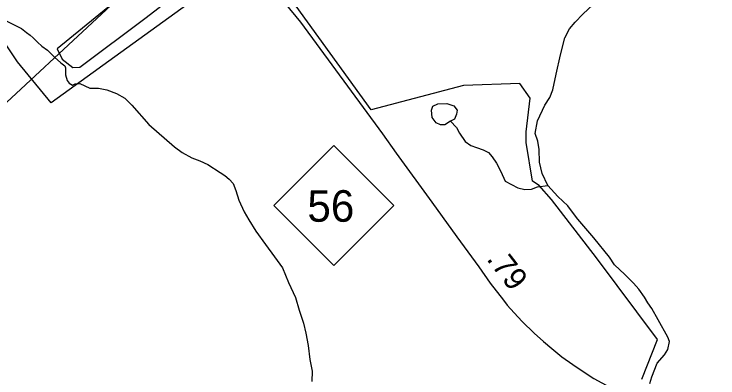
# Model space of a CAD drawing. Extents: x 2056842 to 2160602, y 826753 to 1016856.
# Drawn here: x 2083435 to 2087342, y 866279 to 868296 of the extents above; entities that cross this region are included whole.
import ezdxf

# ---------------------------------------------------------------- set-up
doc = ezdxf.new("R2010")
doc.units = 0
for name, color, linetype in [('Exist Boundary Political City Limit New', 7, 'Continuous'), ('Exist Hydrographic Creek Single Shore', 7, 'Continuous'), ('Exist Hydrographic Lake Shore', 7, 'Continuous'), ('Exist Hydrographic Misc Water Feature', 7, 'Continuous'), ('Exist Road Non-System Type 51', 7, 'Continuous'), ('Exist Road Primary NC Attributed', 7, 'Continuous'), ('Exist Road Primary NC Service Mileage Hundredths English Label', 7, 'Continuous'), ('Exist Road Primary NC Shield CELL', 7, 'Continuous'), ('Exist Road Primary NC Shield Number Label', 7, 'Continuous'), ('Exist Utilities Telephone Line', 7, 'Continuous'), ('Map Preparation Boundary City Limit Buffer Line', 7, 'Continuous')]:
    doc.layers.add(name, color=color, linetype=linetype)

msp = doc.modelspace()

# ---------------------------------------------------------------- linework, layer by layer
at = {"layer": 'Exist Boundary Political City Limit New'}
for points in [[(2084714.8, 868581.4), (2083641.4, 867804.3), (2083454, 868032.2), (2083299.9, 868259.2)], [(2086919.5, 866272.4), (2087006.9, 866490.9), (2086667, 866945.4), (2086417.6, 867267.5), (2086349.6, 867344.8), (2086312.8, 867368.8), (2086278.1, 867585), (2086277.5, 867638.4), (2086278, 867643.6), (2086299.9, 867830.6), (2086242.6, 867911.6), (2085930.4, 867900.1), (2085416.8, 867765.6), (2085000, 868339.6)]]:
    msp.add_lwpolyline(points, dxfattribs=at)
at = {"layer": 'Exist Hydrographic Creek Single Shore'}
msp.add_lwpolyline([(2083349.9, 868279.4), (2083438.3, 868235.6), (2083476, 868215.6), (2083504.3, 868193.9), (2083524.2, 868180), (2083540.2, 868164.2), (2083564.2, 868140.2), (2083588.6, 868118.2), (2083620.8, 868096.4), (2083658.5, 868057.6), (2083693.5, 868025.1), (2083716, 868010.1), (2083719.8, 867997.6), (2083721, 867960.1), (2083729.8, 867927.6), (2083741, 867912.6), (2083758.5, 867902.6), (2083773.5, 867910.1), (2083799.7, 867911.3), (2083856, 867886.3), (2083903.4, 867886.3), (2083949.7, 867876.3), (2084003.4, 867855.1), (2084049.6, 867830.7), (2084089.3, 867792), (2084182.1, 867683.2), (2084326.1, 867560.5), (2084368.4, 867528.5), (2084422.5, 867498.9), (2084466.6, 867483.2), (2084510.1, 867461.3), (2084578.5, 867417.6), (2084604.6, 867401.4), (2084628.6, 867381.6), (2084650.9, 867357.5), (2084666.7, 867317.7), (2084682.9, 867263.8), (2084711.4, 867199.8), (2084737.3, 867156.1), (2084777.4, 867092), (2084829.7, 867018.3), (2084880.2, 866950.3), (2084924.3, 866888.3), (2084958.3, 866806.9), (2084996.9, 866724.8), (2085016.5, 866654.9), (2085041.1, 866582.9), (2085055.3, 866526.8), (2085067.2, 866458.9), (2085076, 866381.2), (2085089.5, 866315.1), (2085087.9, 866258.9)], dxfattribs=at)
at = {"layer": 'Exist Hydrographic Lake Shore'}
for points in [[(2086397.4, 867345.2), (2086366.2, 867411.5), (2086352.4, 867475.2), (2086349.8, 867544.9), (2086341.5, 867590.7), (2086327.4, 867634.1), (2086339.9, 867704.2), (2086381.2, 867790.4), (2086408.6, 867834.2), (2086426.1, 867876.7), (2086444.9, 867962.8), (2086468.6, 868070.3), (2086492.4, 868164.1), (2086517.3, 868215.4), (2086549.8, 868251.6), (2086592.3, 868296.6), (2086648.5, 868350.4), (2086678.5, 868383.5), (2086714.8, 868431), (2086733.5, 868468.5), (2086742.3, 868506)], [(2086964.7, 866247.4), (2086974.7, 866283.7), (2087004.6, 866360), (2087045.9, 866406.2), (2087064.6, 866436.2), (2087073.4, 866481.2), (2087063.4, 866503.7), (2087010.9, 866601.2), (2086974.7, 866662.6), (2086953.4, 866695.1), (2086934.3, 866726.7), (2086902, 866770.7), (2086873.9, 866804.7), (2086826, 866852.3), (2086767.7, 866906.3), (2086739.4, 866948.3), (2086652.3, 867054.9), (2086563.6, 867158.7), (2086539.8, 867190.2), (2086508.6, 867232.7), (2086453.6, 867284), (2086397.4, 867345.2)]]:
    msp.add_lwpolyline(points, dxfattribs=at)
at = {"layer": 'Exist Hydrographic Misc Water Feature'}
for points in [[(2085857.6, 867701.7), (2085825.1, 867682.9), (2085801.4, 867682.9), (2085777.7, 867692.9), (2085756.4, 867722.9), (2085751.4, 867764.2), (2085760.2, 867785.4), (2085786.4, 867799.2), (2085836.4, 867800.4), (2085875.1, 867786.7), (2085893.9, 867762.9), (2085891.4, 867740.4), (2085880.1, 867714.2), (2085857.6, 867701.7)], [(2085857.6, 867701.7), (2085891.5, 867667.7), (2085907.5, 867635.6), (2085939.7, 867589.8), (2085969.6, 867567.8), (2086001.8, 867556.1), (2086037.9, 867544.1), (2086068, 867528.1), (2086088.3, 867504.4), (2086111.9, 867470.4), (2086136.3, 867422.4), (2086160.3, 867370.5), (2086231.2, 867332.7), (2086269.9, 867322.7), (2086306.2, 867325.2), (2086339.9, 867337.7), (2086397.4, 867345.2)]]:
    msp.add_lwpolyline(points, dxfattribs=at)
at = {"layer": 'Exist Road Non-System Type 51'}
msp.add_lwpolyline([(2084593.6, 868819.8), (2084372.1, 868648), (2083954.7, 868332.1), (2083674.3, 868103.5), (2083702.3, 868046.3), (2083760.5, 868000.6), (2083799.9, 868002.7), (2084167.5, 868277), (2084694.1, 868683.5)], dxfattribs=at)
at = {"layer": 'Exist Road Primary NC Attributed'}
msp.add_lwpolyline([(2084851.1, 868465), (2085025.1, 868251.2), (2085479.5, 867632.3), (2085556.7, 867525.5), (2085753.1, 867254.1), (2085810.8, 867172.9), (2085891.9, 867061.6), (2086014.4, 866893.7), (2086077.1, 866804.8), (2086151, 866709.1), (2086172.2, 866681.6), (2086210.8, 866638.6), (2086255.1, 866591), (2086322.8, 866526.1), (2086373.1, 866481.3), (2086420.7, 866441), (2086476.1, 866396.3), (2086536, 866352.6), (2086604.8, 866307.3), (2086654, 866275.4), (2086854.9, 866166.9), (2086913.1, 866138.3), (2086965.1, 866108.7), (2087019.4, 866084)], dxfattribs=at)
at = {"layer": 'Exist Road Primary NC Shield CELL'}
msp.add_lwpolyline([(2084876, 867234.4), (2085209, 867567.4), (2085542, 867234.4), (2085209, 866901.4)], close=True, dxfattribs=at)
at = {"layer": 'Exist Utilities Telephone Line'}
msp.add_lwpolyline([(2070574.6, 855889.8), (2073540.2, 858741.1), (2079471.4, 864196.3), (2082575.1, 867047.6), (2086740, 870917.2), (2087764.9, 872677.4), (2089015.1, 875921.4), (2089705.6, 877143.4), (2092053.4, 881391.2), (2094430.2, 885697.2), (2096843.4, 888330.3), (2097766.5, 889363.1), (2100637.6, 891101.5), (2103123.5, 892599.9), (2104820.7, 893625.5), (2107244.8, 895109.3), (2108287.8, 895378.4), (2108625.8, 895633), (2109723.4, 896782.2), (2110232.2, 897204.1), (2110707.5, 898076.3)], dxfattribs=at)
at = {"layer": 'Map Preparation Boundary City Limit Buffer Line'}
for points in [[(2084714.8, 868581.4), (2083641.4, 867804.3), (2083454, 868032.2), (2083299.9, 868259.2)], [(2086919.5, 866272.4), (2087006.9, 866490.9), (2086667, 866945.4), (2086417.6, 867267.5), (2086349.6, 867344.8), (2086312.8, 867368.8), (2086278.1, 867585), (2086277.5, 867638.4), (2086278, 867643.6), (2086299.9, 867830.6), (2086242.6, 867911.6), (2085930.4, 867900.1), (2085416.8, 867765.6), (2085000, 868339.6)]]:
    msp.add_lwpolyline(points, dxfattribs=at)

# ---------------------------------------------------------------- texts
at = {"layer": 'Exist Road Primary NC Service Mileage Hundredths English Label'}
msp.add_text('.79', height=125, rotation=307.6656, dxfattribs=at).set_placement((2086054, 866936.9))
at = {"layer": 'Exist Road Primary NC Shield Number Label'}
msp.add_text('56', height=175, dxfattribs=at).set_placement((2085063.1, 867144.7))

doc.saveas('drawing.dxf')
